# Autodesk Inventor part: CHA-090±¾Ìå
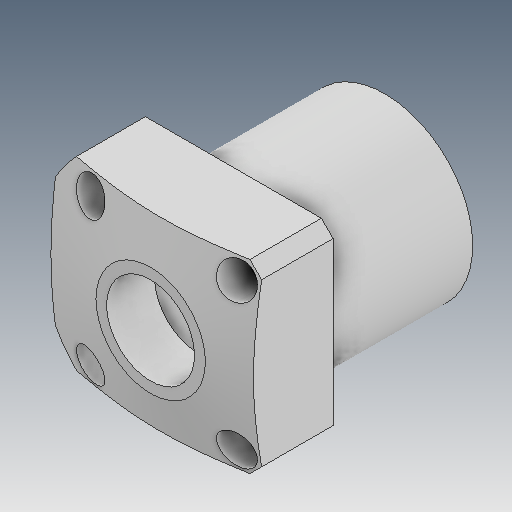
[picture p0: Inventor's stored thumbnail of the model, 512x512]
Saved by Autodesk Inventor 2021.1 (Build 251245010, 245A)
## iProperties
Created: 2019-05
Part Number: CHA-090±¾Ìå
Material: Ogólny
Document SubType Name: Modeling
Designer: user
Density: 1 g/cm^3
Appearance: Domyślna
Author: user
Revision Number: ÈÎºÎ
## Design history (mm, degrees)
feature "ÊäÈë1"
node "Bryła1"
